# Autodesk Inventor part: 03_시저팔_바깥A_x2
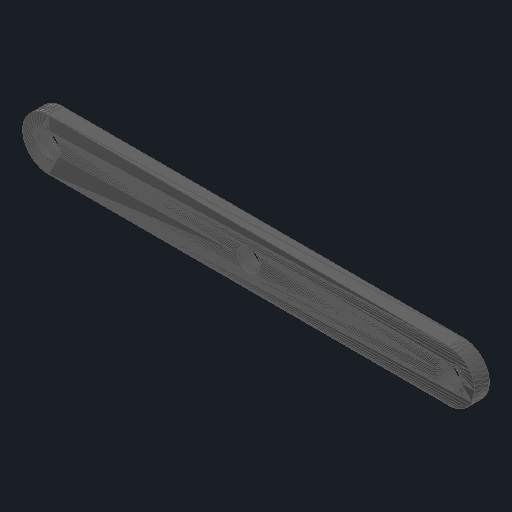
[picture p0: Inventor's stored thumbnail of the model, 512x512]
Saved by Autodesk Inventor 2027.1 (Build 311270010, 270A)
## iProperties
Created: 2026-11
Part Number: 03_시저팔_바깥A_x2
Material: 일반
Document SubType Name: Modeling
Designer: djshs
Density: 1 g/cm^3
Appearance: 기본값
Author: djshs
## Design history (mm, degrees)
node "03_시저팔_바깥A_x2"
  node "MeshFeature1"
